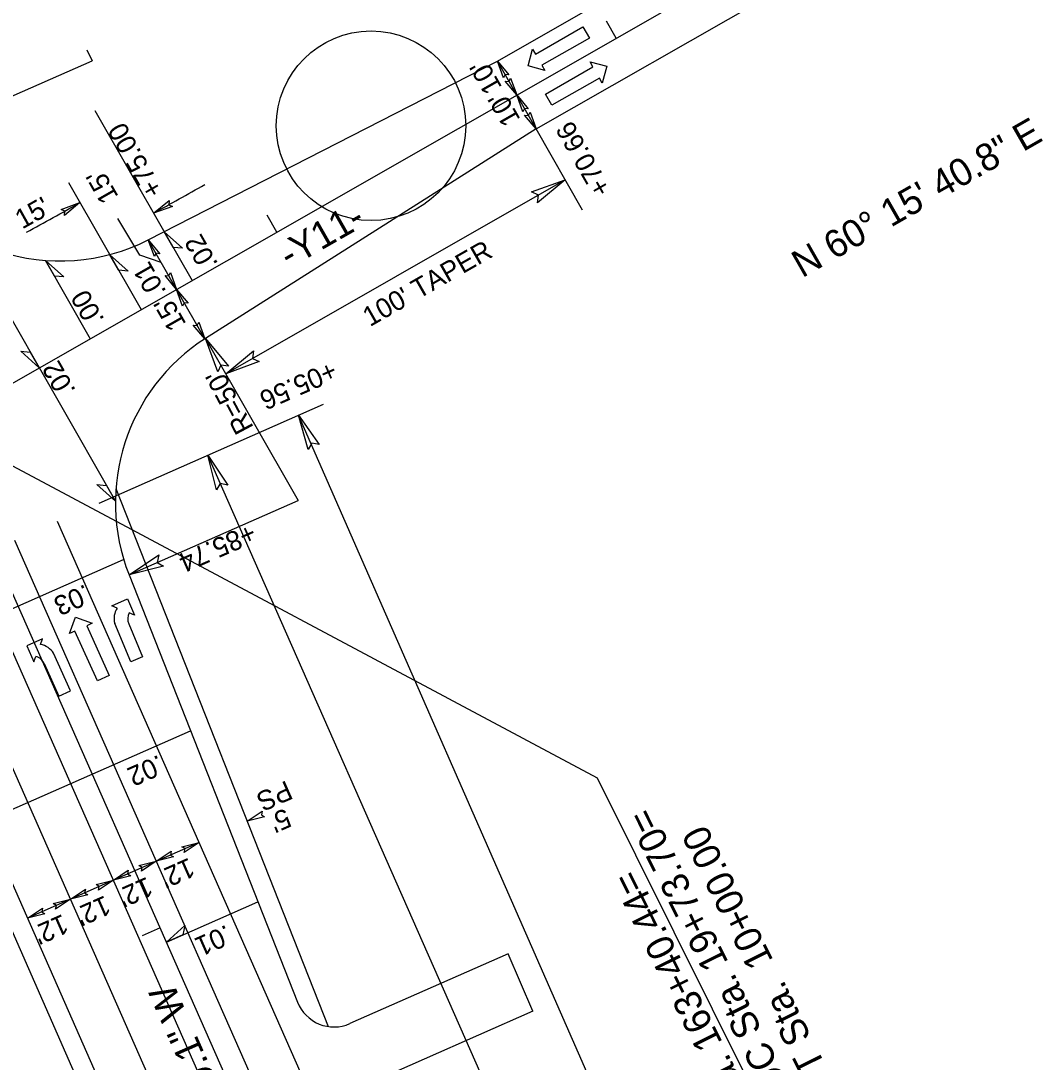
# Model space of a CAD drawing. Extents: x 472216 to 481979, y 489069 to 507339.
# Drawn here: x 475762.8 to 476021.2, y 502065.2 to 502331.6 of the extents above; entities that cross this region are included whole.
import ezdxf

# ---------------------------------------------------------------- set-up
doc = ezdxf.new("R2010")
doc.units = 0
for name, color, linetype in [('Old_Level_12', 7, 'Continuous'), ('Prop Drainage Structure Drop Inlet Grate 2 Narrow Slots and Sag Grates 840 24 CELL', 7, 'Continuous'), ('Prop Drainage Structure Drop Inlet Grate 2 Wide Slots and Sag Grates 840 22 Label', 7, 'Continuous'), ('Prop Drainage Structure Outlet Berm Ditch 850 10 CELL', 7, 'Continuous'), ('Prop Drainage Structure Pipe CSP 15in', 7, 'Continuous'), ('Prop Drainage Structure Pipe RCP 15in Class III Label', 7, 'Continuous'), ('Prop Drainage Structure Pipe RCP 24in Class III Label', 7, 'Continuous'), ('Prop Drainage Structure Pipe Side Drain 15in Label', 7, 'Continuous'), ('Prop Erosion Embankment Toe Protection CELL', 7, 'Continuous'), ('Prop Erosion Embankment Toe Protection Label', 7, 'Continuous'), ('Sheet Block Revision CELL', 7, 'Continuous'), ('Sheet North Arrow Point CELL', 7, 'Continuous'), ('Sheet PE Seal Cell', 7, 'Continuous'), ('Sheet Plan And Profile CELL', 7, 'Continuous'), ('Sheet Plot Border Outside CELL', 7, 'Continuous')]:
    doc.layers.add(name, color=color, linetype=linetype)

msp = doc.modelspace()

# ---------------------------------------------------------------- linework, layer by layer
at = {"layer": 'Old_Level_12'}
for p, q in [((475741.43, 502227.96), (475910.23, 502137.98)), ((475910.23, 502137.98), (475968.37, 502021.07))]:
    msp.add_line(p, q, dxfattribs=at)
at = {"layer": 'Prop Drainage Structure Drop Inlet Grate 2 Narrow Slots and Sag Grates 840 24 CELL'}
for points in [[(475799.43, 502277.63), (475804.15, 502273.41), (475801.73, 502273.61)], [(475785.48, 502271.81), (475790.2, 502267.59), (475787.78, 502267.79)], [(475769.07, 502270.3), (475773.78, 502266.08), (475771.36, 502266.28)], [(475767.48, 502242.84), (475762.77, 502247.06), (475765.19, 502246.86)], [(475786.96, 502208.75), (475782.24, 502212.97), (475784.66, 502212.77)], [(475800, 502095.92), (475804.68, 502100.17), (475804.23, 502097.78)]]:
    msp.add_lwpolyline(points, close=True, dxfattribs=at)
at = {"layer": 'Prop Drainage Structure Drop Inlet Grate 2 Wide Slots and Sag Grates 840 22 Label'}
for p, q in [((475781.7, 502308.67), (475799.24, 502277.97)), ((475774.95, 502290.25), (475793.53, 502257.73)), ((475799.24, 502277.97), (475806.55, 502265.17)), ((475748.18, 502276.62), (475786.96, 502208.75)), ((475769.07, 502270.3), (475780.5, 502250.29)), ((475731.6, 502168.47), (475789.07, 502193.84)), ((475753.57, 502126.8), (475806.17, 502150.02)), ((475800, 502095.92), (475823.43, 502106.26))]:
    msp.add_line(p, q, dxfattribs=at)
for points in [[(475773.05, 502283.37), (475777.89, 502285.1), (475773.9, 502281.82), (475774.02, 502282.92)], [(475801.56, 502284.09), (475796.71, 502282.39), (475800.73, 502285.65), (475800.6, 502284.55)]]:
    msp.add_lwpolyline(points, close=True, dxfattribs=at)
for centre, radius, start in [((475359.26, 503080.35), 910, 298.73219), ((475439.98, 502878.08), 682.5, 298.36128)]:
    msp.add_arc(centre, radius, start, 299.67664, dxfattribs=at)
at = {"layer": 'Prop Drainage Structure Outlet Berm Ditch 850 10 CELL'}
for points in [[(475886.22, 502317.01), (475884.66, 502321.3), (475887.6, 502317.77), (475886.62, 502317.87)], [(475888.06, 502316.91), (475889.62, 502312.62), (475886.68, 502316.15), (475887.66, 502316.05)], [(475891.18, 502308.33), (475889.62, 502312.62), (475892.56, 502309.09), (475891.58, 502309.19)], [(475893.02, 502308.23), (475894.58, 502303.94), (475891.64, 502307.47), (475892.62, 502307.37)], [(475893.42, 502287.83), (475902.02, 502290.91), (475894.93, 502285.07), (475895.14, 502287.02)], [(475796.92, 502271.27), (475795.37, 502275.56), (475798.3, 502272.03), (475797.32, 502272.13)], [(475801.04, 502267.2), (475802.6, 502262.91), (475799.66, 502266.44), (475800.64, 502266.34)], [(475804.16, 502258.61), (475802.6, 502262.91), (475805.54, 502259.37), (475804.56, 502259.48)], [(475808.27, 502254.54), (475809.83, 502250.25), (475806.89, 502253.78), (475807.87, 502253.68)], [(475813.13, 502241.78), (475810.01, 502250.37), (475815.89, 502243.3), (475813.93, 502243.51)], [(475823.77, 502244.43), (475815.19, 502241.31), (475822.25, 502247.19), (475822.05, 502245.23)], [(475836.23, 502221.92), (475833.76, 502230.71), (475839.1, 502223.23), (475837.16, 502223.58)], [(475812.82, 502211.62), (475810.6, 502220.48), (475815.72, 502212.84), (475813.79, 502213.25)], [(475799.3, 502192.1), (475790.44, 502189.9), (475798.08, 502195), (475797.67, 502193.08)], [(475825.1, 502127.99), (475820.67, 502126.88), (475824.49, 502129.44), (475824.29, 502128.47)], [(475803.97, 502120.35), (475808.4, 502121.46), (475804.58, 502118.9), (475804.79, 502119.87)], [(475801.85, 502117.72), (475797.42, 502116.62), (475801.24, 502119.18), (475801.03, 502118.21)], [(475792.99, 502115.51), (475797.42, 502116.62), (475793.6, 502114.06), (475793.81, 502115.02)], [(475790.87, 502112.88), (475786.44, 502111.77), (475790.26, 502114.33), (475790.06, 502113.37)], [(475779.89, 502108.03), (475775.46, 502106.92), (475779.28, 502109.48), (475779.08, 502108.52)], [(475782.01, 502110.66), (475786.44, 502111.77), (475782.63, 502109.21), (475782.83, 502110.18)], [(475771.04, 502105.82), (475775.46, 502106.92), (475771.65, 502104.37), (475771.85, 502105.33)], [(475768.92, 502103.19), (475764.49, 502102.08), (475768.3, 502104.64), (475768.1, 502103.67)]]:
    msp.add_lwpolyline(points, close=True, dxfattribs=at)
at = {"layer": 'Prop Drainage Structure Pipe RCP 15in Class III Label'}
for p, q in [((476004.65, 501647.13), (475761.2, 502198.67)), ((475993.67, 501642.28), (475750.22, 502193.82))]:
    msp.add_line(p, q, dxfattribs=at)
at = {"layer": 'Prop Drainage Structure Pipe RCP 24in Class III Label'}
for p, q in [((475884.66, 502321.3), (476028.98, 502403.75)), ((475894.58, 502303.94), (476038.9, 502386.39)), ((475795.37, 502275.56), (475884.66, 502321.3)), ((475894.58, 502303.94), (475810.01, 502250.37)), ((475790.44, 502189.9), (475833.56, 502080.57)), ((475830.54, 501952.44), (475752.89, 502128.36)), ((475887.44, 502092.99), (475846.9, 502075.09)), ((475893.69, 502078.25), (475887.44, 502092.99)), ((475893.69, 502078.25), (475852.05, 502059.88))]:
    msp.add_line(p, q, dxfattribs=at)
for centre, radius, start, end in [((475772.76, 502320.16), 50, 206.3614, 296.8763), ((475836.95, 502208.25), 50, 122.6011, 201.5258), ((475842.87, 502084.24), 10, 201.5258, 293.8164)]:
    msp.add_arc(centre, radius, start, end, dxfattribs=at)
at = {"layer": 'Prop Drainage Structure Pipe Side Drain 15in Label'}
for p, q in [((475894.4, 502323.08), (475906.56, 502330.02)), ((475906.56, 502330.02), (475908.19, 502327.16)), ((475908.19, 502327.16), (475896.04, 502320.21)), ((475892.51, 502320.04), (475893.66, 502324.38)), ((475893.66, 502324.38), (475894.4, 502323.08)), ((475896.78, 502318.91), (475892.51, 502320.04)), ((475896.04, 502320.21), (475896.78, 502318.91)), ((475896.96, 502312.87), (475909.11, 502319.82)), ((475909.11, 502319.82), (475908.37, 502321.12)), ((475908.37, 502321.12), (475912.64, 502319.99)), ((475912.64, 502319.99), (475911.49, 502315.65)), ((475910.75, 502316.95), (475898.59, 502310.01)), ((475911.49, 502315.65), (475910.75, 502316.95)), ((475898.59, 502310.01), (475896.96, 502312.87)), ((475786.02, 502181.95), (475790.06, 502183.71)), ((475787.39, 502181.39), (475786.02, 502181.95)), ((475790.06, 502183.71), (475791.85, 502179.58)), ((475775.23, 502174.91), (475776.77, 502179.05)), ((475776.77, 502179.05), (475780.98, 502177.5)), ((475791.85, 502179.58), (475790.47, 502180.14)), ((475780.98, 502177.5), (475779.61, 502176.88)), ((475779.61, 502176.88), (475785.36, 502164.12)), ((475790.88, 502167.67), (475786.8, 502177.4)), ((475790.38, 502177.39), (475793.93, 502168.95)), ((475768.34, 502173.49), (475764.3, 502171.73)), ((475767.81, 502172.1), (475768.34, 502173.49)), ((475776.6, 502175.52), (475775.23, 502174.91)), ((475782.35, 502162.76), (475776.6, 502175.52)), ((475764.3, 502171.73), (475766.11, 502167.6)), ((475766.11, 502167.6), (475766.63, 502168.99)), ((475775.48, 502160.2), (475771.14, 502169.82)), ((475793.93, 502168.95), (475790.88, 502167.67)), ((475768.71, 502167.19), (475772.47, 502158.84)), ((475785.36, 502164.12), (475782.35, 502162.76)), ((475772.47, 502158.84), (475775.48, 502160.2))]:
    msp.add_line(p, q, dxfattribs=at)
for centre, radius, start, end in [((475791.87, 502178.68), 5.25, 148.818, 194.1297), ((475793.38, 502178.66), 3.27, 153.1476, 202.8058), ((475766.75, 502166.97), 5.25, 32.9354, 78.247), ((475765.73, 502165.86), 3.27, 24.2593, 73.9175)]:
    msp.add_arc(centre, radius, start, end, dxfattribs=at)
at = {"layer": 'Prop Erosion Embankment Toe Protection CELL'}
for p, q in [((475787.1, 502212.01), (475841.39, 502074.35)), ((475829.51, 501942.39), (475740.49, 502144.06))]:
    msp.add_line(p, q, dxfattribs=at)
at = {"layer": 'Prop Erosion Embankment Toe Protection Label'}
for p, q in [((475779.65, 502324.17), (475781.03, 502321.39)), ((475810.01, 502250.37), (475833.71, 502208.9)), ((475893.32, 501929.06), (475772.18, 502203.52)), ((475982.69, 501637.44), (475739.25, 502188.98))]:
    msp.add_line(p, q, dxfattribs=at)
at = {"layer": 'Sheet Block Revision CELL'}
for p, q in [((475727.96, 502297.96), (475781.03, 502321.39)), ((475894.58, 502303.94), (475884.66, 502321.3)), ((475906.43, 502283.19), (475894.58, 502303.94)), ((475902.02, 502290.91), (475815.19, 502241.31)), ((475793.23, 502271.61), (475787.62, 502281.03)), ((475809.81, 502250.28), (475795.37, 502275.56)), ((475798.68, 502269.77), (475793.23, 502271.61)), ((475782.78, 502208.2), (475840.15, 502233.52)), ((476046.78, 501745.57), (475833.77, 502230.7)), ((475931.78, 501945.95), (475810.6, 502220.48)), ((475790.44, 502189.9), (475833.71, 502208.9)), ((475808.4, 502121.46), (475786.44, 502111.77)), ((475786.44, 502111.77), (475764.49, 502102.08))]:
    msp.add_line(p, q, dxfattribs=at)
at = {"layer": 'Sheet North Arrow Point CELL'}
for p, q in [((475741.43, 502227.96), (476033.34, 502394.73)), ((475999.16, 501644.71), (475755.71, 502196.25))]:
    msp.add_line(p, q, dxfattribs=at)
msp.add_arc((486928.47, 508069.92), 12700, 206.801639, 209.062037, dxfattribs=at)
at = {"layer": 'Sheet PE Seal Cell'}
for p, q in [((475915.09, 502327.17), (475912.61, 502331.51)), ((475915.09, 502327.17), (475912.61, 502331.51)), ((475828.26, 502277.57), (475825.78, 502281.91)), ((475828.26, 502277.57), (475825.78, 502281.91)), ((475828.26, 502277.57), (475825.78, 502281.91)), ((475798.38, 502099.59), (475793.81, 502097.57))]:
    msp.add_line(p, q, dxfattribs=at)
at = {"layer": 'Sheet Plot Border Outside CELL'}
msp.add_circle((475852.34, 502304.75), 24.24, dxfattribs=at)

# ---------------------------------------------------------------- texts
at = {"layer": 'Old_Level_12'}
for s, p in [('-Y10B- POC Sta. 19+73.70=', (475976.77, 502024.6)), ('-Y11- POT Sta.  10+00.00', (475986.17, 502029.27)), ('-L- POC Sta. 163+40.44= ', (475967.37, 502019.92))]:
    msp.add_text(s, height=7, rotation=116.4407, dxfattribs=at).set_placement(p)
at = {"layer": 'Prop Drainage Structure Drop Inlet Grate 2 Narrow Slots and Sag Grates 840 24 CELL'}
for s, rotation, p in [('.02', 119.7387, (475813.34, 502269.42)), ('.01', 119.7387, (475800.11, 502262.34)), ('.00', 119.7387, (475784.26, 502255.21)), ('.02', 119.7387, (475776.94, 502237.06)), ('.03', 203.8164, (475779.24, 502187.58)), ('.02', 203.8164, (475798.04, 502143.95)), ('.01', 203.8164, (475815.35, 502100.48))]:
    msp.add_text(s, height=5, rotation=rotation, dxfattribs=at).set_placement(p)
at = {"layer": 'Prop Drainage Structure Drop Inlet Grate 2 Wide Slots and Sag Grates 840 22 Label'}
for s, rotation, p in [('+75.00', 119.6153, (475799.33, 502288.12)), ("15'", 29.2438, (475763.11, 502278.19))]:
    msp.add_text(s, height=5, rotation=rotation, dxfattribs=at).set_placement(p)
at = {"layer": 'Prop Drainage Structure Pipe CSP 15in'}
for s, rotation, p in [("10'", 119.7387, (475885.98, 502314.61)), ("10'", 119.7387, (475890.67, 502306.4)), ('+70.66', 119.7387, (475913.94, 502288.45)), ("15'", 119.7387, (475787.86, 502286.64)), ("100' TAPER", 29.7387, (475852.07, 502253.24)), ("15'", 119.7387, (475805.19, 502254.07)), ('+05.56', 203.7053, (475842.27, 502244.76)), ("R=50'", 118.1079, (475822.41, 502227.57)), ('+85.74', 203.7053, (475821.56, 502203.21)), ('PS', 203.8164, (475830.75, 502137.39)), ("5'", 203.8164, (475830.43, 502130.32)), ("12'", 203.8164, (475805.81, 502117.64)), ("12'", 203.8164, (475795.08, 502112.76)), ("12'", 203.8164, (475784.28, 502107.99)), ("12'", 203.8164, (475773.47, 502103.22))]:
    msp.add_text(s, height=5, rotation=rotation, dxfattribs=at).set_placement(p)
at = {"layer": 'Sheet Plan And Profile CELL'}
for s, rotation, p in [('N 60%%d 15\' 40.8" E', 29.7387, (475962.62, 502265.72)), ('-Y11-', 29.7387, (475831.38, 502268.15)), ('N 23%%d 48\' 59.1" W', 113.8164, (475831.56, 502018.22))]:
    msp.add_text(s, height=7, rotation=rotation, dxfattribs=at).set_placement(p)

doc.saveas('drawing.dxf')
